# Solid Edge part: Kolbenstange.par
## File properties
Username: bmolnar
Dokumentum tartalom típus: 0
Author: bmolnar
Last saved by: bmolnar
Revision: 82
Sűrűség: 0,000 kg/m^3
Pontosság: 0,990
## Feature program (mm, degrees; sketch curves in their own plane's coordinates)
base feature "unnamed BaseFeature 1"
sketch for "unnamed Protrusion 1" plane through (0, 0, -17.4) normal (0, 0, -1) x-axis (0, 1, 0)
  circle centre (0, 0) radius 20
extrude "unnamed Protrusion 1" add finite 17.45 along +normal
sketch for "Kihúzás_2" #1 plane through (0, 0, -17.4) normal (0, 0, -1) x-axis (0, 1, 0)
  circle centre (0, 0) radius 6
sketch for "Kihúzás_2" #2 plane through (0, 0, -17.4) normal (0, 0, -1) x-axis (0, 1, 0)
  circle centre (0, 0) radius 20
extrude "Kihúzás_2" add finite 12.55 along -normal
sketch for "Furat_1" plane through (0, 0, 39.9) normal (0, 0, 1) x-axis (0, -1, 0)
  hole centre (0, 0) bore radius 2.4585
hole "Furat_1" nominal diameter 6 finite  ThreadDepth = 12.5 mm; VBottomAngle = 118 deg
chamfer "Letörés_1" setback 0.5  SetBackValue2 = 45 deg
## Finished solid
Body 1: solid body, 17 faces, 23 edges, 8 vertices.
  Faces by surface: plane 7, cylinder 5, cone 3, torus 2
  Edges by curve: circle 13, line 6, curve on surface 2, ellipse 2
Bounding box of the edges (mm; curved faces can reach further): 40.000 x 40.000 x 77.250, from (-20, -20, -34.85) to (20, 20, 42.4).
Cylindrical faces by radius (mm): R2.4585 x2, R3.125 x1, R6 x1, R20 x1
Conical faces (half-angle, radius in mm at the cone's reference point): 45 deg R2.9585 x1, 45 deg R3.225 x1, 59 deg R2.4585 x1
Toroidal faces (ring radius, tube radius in mm): R2.925 r0.2 x1, R4.7 r1.3 x1
Planar faces by outward normal: +x 1, +z 2, -x 1, -z 1, oblique 2
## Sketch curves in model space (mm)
circle centre (0, 0, -17.4) radius 6
circle centre (0, 0, -17.4) radius 20
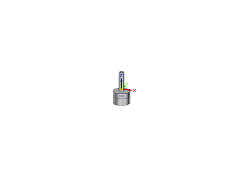
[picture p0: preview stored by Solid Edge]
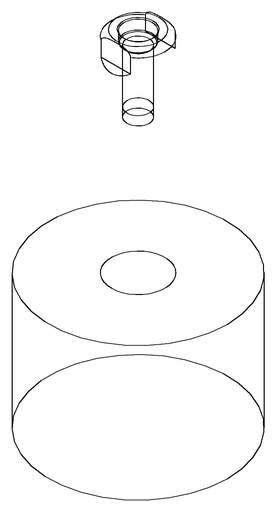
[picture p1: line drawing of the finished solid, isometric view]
